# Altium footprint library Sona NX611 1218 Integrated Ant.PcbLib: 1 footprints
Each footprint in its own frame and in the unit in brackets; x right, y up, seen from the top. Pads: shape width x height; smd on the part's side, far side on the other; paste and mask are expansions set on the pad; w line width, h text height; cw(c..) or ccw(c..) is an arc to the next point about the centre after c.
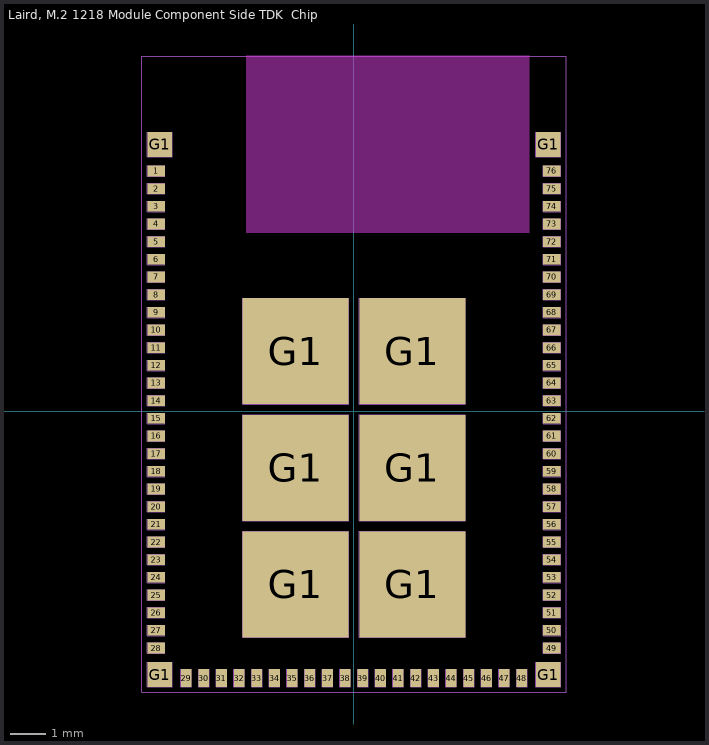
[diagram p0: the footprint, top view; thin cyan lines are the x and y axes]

## Laird, M.2 1218 Module Component Side TDK  Chip Ant. [mm] "Laird, M.2 1218 Module Component Side  TDK Chip Ant."
height 0.4
pads (86):
  rect 0.5x0.3 smd mask+0.051: 1(-5.6,6.8) 2(-5.6,6.3) 3(-5.6,5.8) 4(-5.6,5.3) 5(-5.6,4.8) 6(-5.6,4.3) 7(-5.6,3.8) 8(-5.6,3.3) 9(-5.6,2.8) 10(-5.6,2.3) 11(-5.6,1.8) 12(-5.6,1.3) 13(-5.6,0.8) 14(-5.6,0.3) 15(-5.6,-0.2) 16(-5.6,-0.7) 17(-5.6,-1.2) 18(-5.6,-1.7) 19(-5.6,-2.2) 20(-5.6,-2.7) 21(-5.6,-3.2) 22(-5.6,-3.7) 23(-5.6,-4.2) 24(-5.6,-4.7) 25(-5.6,-5.2) 26(-5.6,-5.7) 27(-5.6,-6.2) 28(-5.6,-6.7) 49(5.6,-6.7) 50(5.6,-6.2) 51(5.6,-5.7) 52(5.6,-5.2) 53(5.6,-4.7) 54(5.6,-4.2) 55(5.6,-3.7) 56(5.6,-3.2) 57(5.6,-2.7) 58(5.6,-2.2) 59(5.6,-1.7) 60(5.6,-1.2) 61(5.6,-0.7) 62(5.6,-0.2) 63(5.6,0.3) 64(5.6,0.8) 65(5.6,1.3) 66(5.6,1.8) 67(5.6,2.3) 68(5.6,2.8) 69(5.6,3.3) 70(5.6,3.8) 71(5.6,4.3) 72(5.6,4.8) 73(5.6,5.3) 74(5.6,5.8) 75(5.6,6.3) 76(5.6,6.8)
  rect 0.3x0.5 smd mask+0.051: 29(-4.749,-7.55) 30(-4.249,-7.55) 31(-3.75,-7.55) 32(-3.249,-7.55) 33(-2.75,-7.55) 34(-2.249,-7.55) 35(-1.749,-7.55) 36(-1.25,-7.55) 37(-0.749,-7.55) 38(-0.25,-7.55) 39(0.251,-7.55) 40(0.751,-7.55) 41(1.25,-7.55) 42(1.751,-7.55) 43(2.25,-7.55) 44(2.751,-7.55) 45(3.251,-7.55) 46(3.75,-7.55) 47(4.251,-7.55) 48(4.75,-7.55)
  rect 0.7x0.7 smd mask+0.051: G1(-5.5,-7.45) G1(-5.5,7.55) G1(5.5,-7.45) G1(5.5,7.55)
  rect 3x3 smd mask+0.051: G1(-1.65,-4.9) G1(-1.65,-1.6) G1(-1.65,1.7) G1(1.65,-1.6) G1(1.65,1.7) G1(1.65,-4.9)
Keep-Out Layer:
  region: -3.046,5.059 4.954,5.059 4.954,10.059 -3.046,10.059
Top Top Assembly/Bottom Assembly:
  drawing of 348 lines, arcs and shapes, not listed
  text ".Designator" at -0.15,-0.1 h1.27
3D body: height 0.01, standoff 0, extent -5.85,-3.35 -5.35,-3.05
3D body: height 0.01, standoff 0, extent -5.85,-3.85 -5.35,-3.55
3D body: height 0.01, standoff 0, extent -5.85,-4.35 -5.35,-4.05
3D body: height 0.01, standoff 0, extent -5.85,-4.85 -5.35,-4.55
3D body: height 0.01, standoff 0, extent -5.85,-2.85 -5.35,-2.55
3D body: height 0.01, standoff 0, extent -5.85,-2.35 -5.35,-2.05
3D body: height 0.01, standoff 0, extent -5.85,-1.85 -5.35,-1.55
3D body: height 0.01, standoff 0, extent -5.85,-5.85 -5.35,-5.55
3D body: height 0.01, standoff 0, extent -5.85,-5.35 -5.35,-5.05
3D body: height 0.01, standoff 0, extent -5.85,-6.35 -5.35,-6.05
3D body: height 0.01, standoff 0, extent -5.85,-6.85 -5.35,-6.55
3D body: height 0.01, standoff 0, extent -5.85,-7.8 -5.15,-7.1
3D body: height 0.01, standoff 0, extent -4.9,-7.8 -4.6,-7.3
3D body: height 0.01, standoff 0, extent -4.4,-7.8 -4.1,-7.3
3D body: height 0.01, standoff 0, extent -3.9,-7.8 -3.6,-7.3
3D body: height 0.01, standoff 0, extent -3.4,-7.8 -3.1,-7.3
3D body: height 0.01, standoff 0, extent -2.9,-7.8 -2.6,-7.3
3D body: height 0.01, standoff 0, extent -2.4,-7.8 -2.1,-7.3
3D body: height 0.01, standoff 0, extent -1.9,-7.8 -1.6,-7.3
3D body: height 0.01, standoff 0, extent -1.4,-7.8 -1.1,-7.3
3D body: height 0.01, standoff 0, extent -0.9,-7.8 -0.6,-7.3
3D body: height 0.01, standoff 0, extent -0.4,-7.8 -0.1,-7.3
3D body: height 0.01, standoff 0, extent 0.1,-7.8 0.4,-7.3
3D body: height 0.01, standoff 0, extent 0.6,-7.8 0.9,-7.3
3D body: height 0.01, standoff 0, extent 1.1,-7.8 1.4,-7.3
3D body: height 0.01, standoff 0, extent 1.6,-7.8 1.9,-7.3
3D body: height 0.01, standoff 0, extent 2.1,-7.8 2.4,-7.3
3D body: height 0.01, standoff 0, extent 4.1,-7.8 4.4,-7.3
3D body: height 0.01, standoff 0, extent 3.6,-7.8 3.9,-7.3
3D body: height 0.01, standoff 0, extent 3.1,-7.8 3.4,-7.3
3D body: height 0.01, standoff 0, extent 2.6,-7.8 2.9,-7.3
3D body: height 0.01, standoff 0, extent 4.6,-7.8 4.9,-7.3
3D body: height 0.01, standoff 0, extent 5.15,-7.8 5.85,-7.1
3D body: height 0.01, standoff 0, extent 5.35,-6.85 5.85,-6.55
3D body: height 0.01, standoff 0, extent 5.35,-6.35 5.85,-6.05
3D body: height 0.01, standoff 0, extent 5.35,-5.85 5.85,-5.55
3D body: height 0.01, standoff 0, extent 5.35,-5.35 5.85,-5.05
3D body: height 0.01, standoff 0, extent -3.15,-6.4 -0.15,-3.4
3D body: height 0.01, standoff 0, extent 0.15,-6.4 3.15,-3.4
3D body: height 0.01, standoff 0, extent 5.35,-4.85 5.85,-4.55
3D body: height 0.01, standoff 0, extent 5.35,-4.35 5.85,-4.05
3D body: height 0.01, standoff 0, extent 5.35,-3.85 5.85,-3.55
3D body: height 0.01, standoff 0, extent 5.35,-3.35 5.85,-3.05
3D body: height 0.01, standoff 0, extent 5.35,-2.85 5.85,-2.55
3D body: height 0.01, standoff 0, extent 5.35,-2.35 5.85,-2.05
3D body: height 0.01, standoff 0, extent 5.35,-1.85 5.85,-1.55
3D body: height 0.01, standoff 0, extent -3.15,-3.1 -0.15,-0.1
3D body: height 0.01, standoff 0, extent 0.15,-3.1 3.15,-0.1
3D body: height 0.01, standoff 0, extent -5.85,-1.35 -5.35,-1.05
3D body: height 0.01, standoff 0, extent -5.85,-0.85 -5.35,-0.55
3D body: height 0.01, standoff 0, extent -5.85,-0.35 -5.35,-0.05
3D body: height 0.01, standoff 0, extent -5.85,0.15 -5.35,0.45
3D body: height 0.01, standoff 0, extent -5.85,0.65 -5.35,0.95
3D body: height 0.01, standoff 0, extent -5.85,1.15 -5.35,1.45
3D body: height 0.01, standoff 0, extent -3.15,0.2 -0.15,3.2
3D body: height 0.01, standoff 0, extent -5.85,1.65 -5.35,1.95
3D body: height 0.01, standoff 0, extent -5.85,2.15 -5.35,2.45
3D body: height 0.01, standoff 0, extent -5.85,2.65 -5.35,2.95
3D body: height 0.01, standoff 0, extent -5.85,3.15 -5.35,3.45
3D body: height 0.01, standoff 0, extent -5.85,3.65 -5.35,3.95
3D body: height 0.01, standoff 0, extent -5.85,4.15 -5.35,4.45
3D body: height 0.01, standoff 0, extent -5.85,4.65 -5.35,4.95
3D body: height 0.01, standoff 0, extent -5.85,5.15 -5.35,5.45
3D body: height 0.01, standoff 0, extent -5.85,5.65 -5.35,5.95
3D body: height 0.01, standoff 0, extent -5.85,6.15 -5.35,6.45
3D body: height 0.01, standoff 0, extent -5.85,6.65 -5.35,6.95
3D body: height 0.01, standoff 0, extent -5.85,7.2 -5.15,7.9
3D body: height 0.01, standoff 0, extent 5.35,-1.35 5.85,-1.05
3D body: height 0.01, standoff 0, extent 5.35,-0.85 5.85,-0.55
3D body: height 0.01, standoff 0, extent 5.35,-0.35 5.85,-0.05
3D body: height 0.01, standoff 0, extent 5.35,0.15 5.85,0.45
3D body: height 0.01, standoff 0, extent 5.35,0.65 5.85,0.95
3D body: height 0.01, standoff 0, extent 5.35,1.15 5.85,1.45
3D body: height 0.01, standoff 0, extent 0.15,0.2 3.15,3.2
3D body: height 0.01, standoff 0, extent 5.35,1.65 5.85,1.95
3D body: height 0.01, standoff 0, extent 5.35,2.15 5.85,2.45
3D body: height 0.01, standoff 0, extent 5.35,2.65 5.85,2.95
3D body: height 0.01, standoff 0, extent 5.35,3.15 5.85,3.45
3D body: height 0.01, standoff 0, extent 5.35,3.65 5.85,3.95
3D body: height 0.01, standoff 0, extent 5.35,4.15 5.85,4.45
3D body: height 0.01, standoff 0, extent 5.35,4.65 5.85,4.95
3D body: height 0.01, standoff 0, extent 5.35,5.15 5.85,5.45
3D body: height 0.01, standoff 0, extent 5.35,5.65 5.85,5.95
3D body: height 0.01, standoff 0, extent 5.35,6.15 5.85,6.45
3D body: height 0.01, standoff 0, extent 5.35,6.65 5.85,6.95
3D body: height 0.01, standoff 0, extent 5.15,7.2 5.85,7.9
3D body "940-00315-R2.0.step": height 1.76, standoff 0, extent -6,-7.95 6,10.05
